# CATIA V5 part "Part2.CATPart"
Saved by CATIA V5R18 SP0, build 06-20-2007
Part number: Part2
Bounding box of the stored display mesh (mm): x -12.5 to 12.5, y -12.31 to 12.31, z 0 to 5
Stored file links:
  D:\Shriniwas\v5_r19\c16_CAT_v5r19\c16_Part\Planer Joint\Part2.CATPart
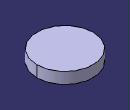
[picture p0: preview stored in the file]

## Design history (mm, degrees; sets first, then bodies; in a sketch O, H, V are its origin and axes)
Body1 (main body)
  Sketch1 on xy-plane, origin (0, 0, 0), H (1, 0, 0), V (0, 1, 0)
    circle A1 centre (0, 0) radius 12.5
    point P1 (0, 12.5)
    radius A1 = 12.5
    coincidence: A1 P1, P1 V
  Pad1: profile Sketch1, direction (0, 0, 1), length 5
